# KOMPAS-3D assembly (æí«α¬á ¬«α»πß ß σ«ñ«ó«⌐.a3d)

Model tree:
1. Эскиз:1
2. Эскиз:2
     Расстояние = 25.5

Referenced files in D:\МОДЕЛЬ ТАНКА Т90\СБОРКИ\СБОРКА ЛИТЬЕ СТАРАЯ\: Сборка корпус.a3d
Referenced files in D:\МОДЕЛЬ ТАНКА Т90\ДЕТАЛИ\ОБЩИЕ ДЕТАЛИ\: подшипник 13-5-4.m3d
Referenced files in D:\МОДЕЛЬ ТАНКА Т90\СБОРКИ\СБОРКА ХОДОВАЯ\: Сборка каток поддерживающий.a3d, Сборка каток с балансиром полностью.a3d, Сборка ленивец с эксцентриком.a3d, Сборка звездочка с осями.a3d, Сборка гусеница30.a3d, Сборка трак мелкий.a3d, Сборка гусеница5.a3d
Referenced files in D:\МОДЕЛЬ ТАНКА Т90\ДЕТАЛИ\ХОДОВАЯ\Каток опорный с балансиром\: рычаг торсион.m3d
Referenced files in D:\МОДЕЛЬ ТАНКА Т90\ДЕТАЛИ\ХОДОВАЯ\Ленивец с эксцентриком\: ось эксцентрика ленивца.m3d
Referenced files in D:\МОДЕЛЬ ТАНКА Т90\ДЕТАЛИ\ХОДОВАЯ\звездочка\: крышка оси звездочки.m3d
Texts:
  Сборка корпус с ходовой
  stalker61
